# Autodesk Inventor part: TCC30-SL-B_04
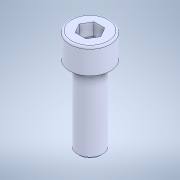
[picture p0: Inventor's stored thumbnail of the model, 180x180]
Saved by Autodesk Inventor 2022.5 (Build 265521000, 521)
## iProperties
Created: 2023-09
Part Number: TCC30-SL-B_04
Material: 一般
Document SubType Name: Modeling
Designer: ImaoCorp
Density: 1 g/cm^3
Appearance: 既定
Author: ImaoCorp
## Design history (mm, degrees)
feature "TCC30-SL-B_04"
node "ソリッド1"
